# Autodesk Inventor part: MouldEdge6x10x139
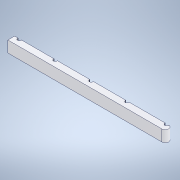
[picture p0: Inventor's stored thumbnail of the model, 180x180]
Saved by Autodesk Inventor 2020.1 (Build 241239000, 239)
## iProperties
Created: 2021-11
Part Number: MouldEdge6x10x139
Material: Generic
Document SubType Name: Modeling
Designer: c14576jb
Density: 1 g/cm^3
Appearance: Default
Author: c14576jb
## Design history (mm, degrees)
sketch "Sketch2" dims "d9" = 10, "d16" = 10, "d23" = 10, "d30" = 10
  geometry: L1 (0, 0)-(139, 0); L2 (139, 0)-(139, -6); L3 (139, -6)-(0, -6); L4 (0, -6)-(0, 0); L5 (3, -6)-(6, -6); L6 (6, -6)-(6, -4); L7 (6, -4)-(3, -4); L8 (3, -4)-(3, -6); L9 (37.75, -6)-(40.75, -6); L10 (40.75, -6)-(40.75, -4); L11 (40.75, -4)-(37.75, -4); L12 (37.75, -4)-(37.75, -6); L13 (69.5, -6)-(72.5, -6); L14 (72.5, -6)-(72.5, -4); L15 (72.5, -4)-(69.5, -4); L16 (69.5, -4)-(69.5, -6); L17 (104.25, -6)-(104.25, -4); L18 (101.25, -6)-(104.25, -6); L19 (104.25, -4)-(101.25, -4); L20 (101.25, -4)-(101.25, -6); L21 (133, -6)-(136, -6); L22 (136, -4)-(133, -4); L23 (133, -4)-(133, -6); L24 (136, -6)-(136, -4); 9 further points
  constraints: 48 end point, 6 horizontal, 4 parallel, 2 perpendicular, 1 point on line, 32 other
  dimensions: "d0" = 139 distance of L2.end L3.end; "d1" = 6 distance of L1.end L2.end; "d2" = 3 distance of L7.end L6.end; "d3" = 2 distance of L6.end L5.end; "d6" = 34.75 distance of L5.start L9.start; "d13" = 66.5 distance of L5.start L13.start; "d20" = 98.25 distance of L5.end L17.start; "d27" = 130 distance of L6.end L22.start
extrude "Extrusion1" new body sketch "Sketch2" distance "d32" = 10; taper "d33" = 0 deg
fillet "Fillet1"
fillet "Fillet2"
fillet "Fillet3"
fillet "Fillet4"
fillet "Fillet5"
fillet "Fillet6"
body "Solid1"
